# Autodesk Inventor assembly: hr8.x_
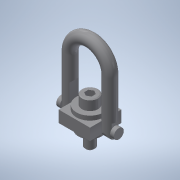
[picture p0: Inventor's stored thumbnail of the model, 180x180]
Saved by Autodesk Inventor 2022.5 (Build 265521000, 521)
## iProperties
Part Number: hr8.x_
Material: 一般
Document SubType Name: Assembly
Designer: ImaoCorp
Sending System: SOLIDWORKS 2017-2017317
MC: AMD64
MC_MODEL: Intel64 Family 6 Model 60 Stepping 3, GenuineIntel
OS: Windows_NT
FRU: Parasolid Version 29.0, build 201,  4-17-2017
FORMAT: text
GUISE: transmit
KEY: hr8
FILE: hr8.x_t
DATE: Mon Jul 01 17:38:43 2019
Author: ImaoCorp
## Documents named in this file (3)
- X:\14_SW2022-Inv2022\00_全2023-1023新製品(TCC)まで\h\hr8\HR8.iam
- X:\14_SW2022-Inv2022\00_全2023-1023新製品(TCC)まで\h\hr8\hr8_01.ipt
- X:\14_SW2022-Inv2022\00_全2023-1023新製品(TCC)まで\h\hr8\hr8_02.ipt
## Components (2 placed, 2 different names)
1. hr8_01
2. hr8_02
